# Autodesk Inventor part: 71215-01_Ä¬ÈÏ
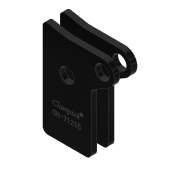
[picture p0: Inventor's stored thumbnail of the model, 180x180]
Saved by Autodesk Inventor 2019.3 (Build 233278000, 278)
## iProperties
Created: 2010-06
Part Number: 71215-01_Ä¬ÈÏ
Material: Ogólny
Document SubType Name: Modeling
Designer: CADENGINEERING4
Density: 1 g/cm^3
Appearance: Gładki — czarny
Author: CADENGINEERING4
Revision Number: ÈÎºÎ
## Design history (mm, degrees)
feature "NONE"
feature "NONE:1"
node "Bryła1"
node "Bryła2"
